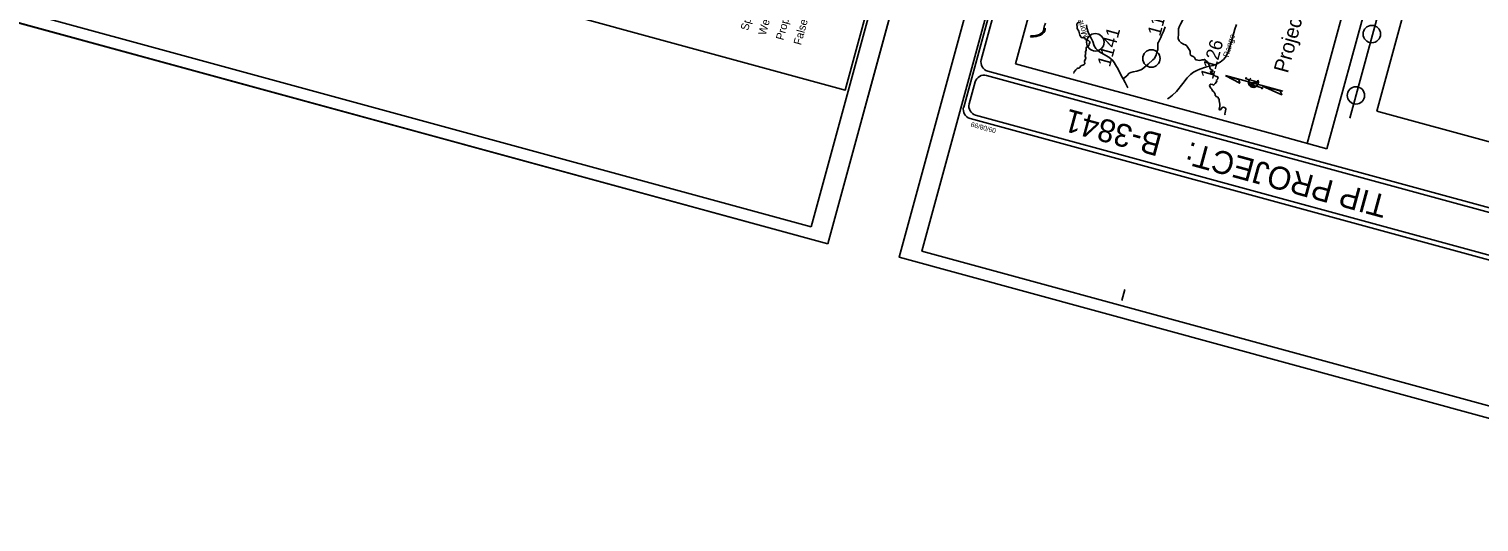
# Model space of a CAD drawing. Extents: x 2076126 to 2079903, y 925480 to 928006.
# Drawn here: x 2077447 to 2079033, y 925480 to 926019 of the extents above; entities that cross this region are included whole.
import ezdxf

# ---------------------------------------------------------------- set-up
doc = ezdxf.new("R2010")
doc.units = 0
for name, color, linetype in [('Default', 7, 'Continuous'), ('Old_Level_11', 7, 'Continuous'), ('Old_Level_31', 7, 'Continuous'), ('Old_Level_32', 7, 'Continuous'), ('Old_Level_50', 7, 'Continuous'), ('Old_Level_59', 7, 'Continuous'), ('Old_Level_8', 7, 'Continuous'), ('Prop Roadway Bridge', 7, 'Continuous'), ('Prop Shade Heavy', 7, 'Continuous'), ('Prop Shade Light', 7, 'Continuous'), ('Sheet Cutting Line CELL', 7, 'Continuous'), ('Sheet North Arrow CELL', 7, 'Continuous'), ('Sheet Plot Border Inside CELL', 7, 'Continuous'), ('Sheet Plot Border Outside CELL', 7, 'Continuous'), ('Sheet Symbology CELL', 7, 'Continuous'), ('Sheet Title CELL', 7, 'Continuous')]:
    doc.layers.add(name, color=color, linetype=linetype)

msp = doc.modelspace()

# ---------------------------------------------------------------- linework, layer by layer
at = {"layer": 'Default'}
for p, q in [((2078643.2, 926410.7), (2078526.1, 925981.2)), ((2078845, 925894.2), (2078962.2, 926323.7)), ((2078984, 926317.8), (2078866.8, 925888.3)), ((2078526.1, 925981.2), (2078816.9, 925901.9)), ((2078866.8, 925888.3), (2078816.9, 925901.9))]:
    msp.add_line(p, q, dxfattribs=at)
at = {"layer": 'Old_Level_31'}
msp.add_line((2078738.5, 925978.5), (2078738.5, 925978.5), dxfattribs=at)
at = {"layer": 'Old_Level_32'}
for points in [[(2078643.9, 925964.6), (2078641.8, 925968.4), (2078638.3, 925975.2), (2078635.6, 925980.2), (2078634.1, 925982.6), (2078632.4, 925985), (2078630.6, 925986.6), (2078628.3, 925988.5), (2078622.4, 925991.8), (2078618, 925994.4), (2078615.9, 925996), (2078614.2, 925998), (2078612.3, 926001), (2078610.7, 926005.5), (2078608.9, 926009.4), (2078606, 926014.7), (2078604.3, 926020.6), (2078603.9, 926023.9)], [(2078643.9, 925964.6), (2078647.8, 925968.1), (2078650.6, 925970.8), (2078652.2, 925971.8), (2078654.7, 925972.4), (2078658.8, 925973.2), (2078661, 925973.8), (2078663.1, 925974.5), (2078664.8, 925975.4), (2078671.1, 925980.9), (2078676.5, 925985.6), (2078678.1, 925987.1), (2078679.1, 925988.9), (2078679.9, 925990.7), (2078680.8, 925993.9), (2078681.8, 925997), (2078681.7, 926000), (2078682, 926003.8), (2078682.4, 926004.9), (2078683.6, 926007.2), (2078685, 926010.1), (2078686.4, 926012.9), (2078687.9, 926016.5), (2078689.8, 926021.8)], [(2078692.3, 925942.9), (2078694.2, 925944), (2078698, 925947), (2078702.1, 925950.8), (2078709.1, 925959.6), (2078713.9, 925965.7), (2078717.5, 925969.5), (2078720.7, 925971.9), (2078724.5, 925974), (2078727.7, 925975.5), (2078733.9, 925977.4), (2078738.5, 925978.5), (2078742.4, 925979.5), (2078746.1, 925980.7), (2078750.1, 925982.9), (2078753.7, 925986), (2078755.7, 925988.5), (2078758.9, 925994), (2078762.7, 926007.2), (2078766.1, 926018.9), (2078767.8, 926024.2)], [(2078649.2, 925954.8), (2078646, 925960.8), (2078643.9, 925964.6)]]:
    msp.add_lwpolyline(points, dxfattribs=at)
at = {"layer": 'Old_Level_50'}
msp.add_line((2078738.5, 925978.5), (2078738.5, 925978.5), dxfattribs=at)
at = {"layer": 'Old_Level_59'}
for points in [[(2078713.5, 926059.2), (2078714.4, 926059.1), (2078715.8, 926059.3), (2078716.8, 926058.9), (2078718.5, 926058), (2078720.6, 926056.5), (2078721.2, 926055.9), (2078721.6, 926055), (2078722, 926053.9), (2078721.6, 926052), (2078720, 926049.2), (2078717.4, 926044.5), (2078716.9, 926043.6), (2078716.1, 926041.1), (2078711.4, 926032.6), (2078709.6, 926030), (2078706.8, 926024.5), (2078705.4, 926022.4), (2078704.6, 926019.5), (2078704.6, 926013.8), (2078704, 926008.7)], [(2078542.3, 926010.5), (2078542.7, 926010.6), (2078546, 926010.6), (2078548.8, 926011), (2078553.5, 926012.5), (2078555.7, 926014.1), (2078557.1, 926015.3), (2078558.3, 926016.7), (2078558.6, 926018.2), (2078558.6, 926020.1)], [(2078542.7, 926011.9), (2078545.2, 926011.8), (2078548.1, 926012.1), (2078552.4, 926013.3), (2078555.1, 926014.9), (2078555.8, 926015.6), (2078556.9, 926017.5), (2078557.7, 926021.6), (2078557.9, 926023.2), (2078558.5, 926024.6), (2078558.9, 926025.6)], [(2078597.1, 926026.5), (2078595.1, 926026.3), (2078594.2, 926025.9), (2078593.8, 926025.5), (2078593.3, 926023.9), (2078593.7, 926022.1), (2078593.7, 926019.7), (2078595.3, 926016.9), (2078596.7, 926012.6), (2078597.4, 926011.3), (2078597.5, 926010.7), (2078597.8, 926010.4), (2078598.5, 926010), (2078599.7, 926009.7), (2078600.6, 926009.8), (2078601.9, 926009.2), (2078602.8, 926007.8), (2078604.3, 926007.1), (2078606.1, 926006.5), (2078607.2, 926005.6), (2078607.3, 926005), (2078607.3, 926004.2), (2078606.7, 926002.9)], [(2078606.7, 926002.9), (2078606.3, 926000.7), (2078606.1, 926000.4), (2078605.6, 926000.3), (2078604.5, 925999.8), (2078603.9, 925999.3), (2078603.6, 925998.4), (2078603.4, 925995.6), (2078602.9, 925994.5), (2078602.8, 925993.5), (2078603, 925992.9), (2078602.3, 925990.4), (2078602.4, 925989.6), (2078603.2, 925987.3), (2078602.9, 925986.2), (2078601.8, 925984.3), (2078601.7, 925983.6), (2078602.1, 925981.3), (2078601.3, 925980.3), (2078597.3, 925978.6), (2078596.4, 925977.1), (2078595.9, 925976.6), (2078594.4, 925976.6), (2078593.6, 925976.2), (2078592.1, 925974.5), (2078590.4, 925972.3), (2078589.9, 925971.1), (2078589.9, 925971.1)], [(2078704, 926008.7), (2078705.2, 926006.3), (2078706.1, 926005.1), (2078707.4, 926004), (2078709.8, 926002.6), (2078710.7, 926002.3), (2078712.1, 926002.1), (2078713.5, 926001), (2078713.6, 926000.5)], [(2078719.9, 925989.5), (2078718.7, 925990), (2078717.7, 925990.7), (2078717.2, 925992.4), (2078717.2, 925994.7), (2078716.9, 925995.9), (2078714.5, 925998.9), (2078713.9, 926000.1), (2078713.5, 926000.6)], [(2078719.9, 925989.5), (2078721.1, 925988.9), (2078722, 925988), (2078723.2, 925985.8), (2078723.9, 925985.4), (2078727.5, 925984.9), (2078729, 925985.1), (2078730.2, 925985.6), (2078732, 925985.6), (2078732.5, 925985.8), (2078733.2, 925985.8), (2078733.6, 925985.4), (2078734, 925984.6), (2078734.5, 925984.5), (2078735.5, 925984.2), (2078736.3, 925983.4), (2078738, 925979.6), (2078738.5, 925978.5), (2078738.9, 925976.9), (2078739.7, 925975.1), (2078740.9, 925974.5), (2078741.5, 925974.1), (2078741.9, 925973.4), (2078741.9, 925973), (2078741.4, 925972.8), (2078740, 925972.9), (2078739.6, 925972.7), (2078739.6, 925972.1), (2078739.8, 925971.5), (2078740.5, 925971), (2078741.1, 925970.8), (2078742, 925970.6), (2078742.1, 925970.2), (2078742.2, 925969.7), (2078743.9, 925968.2), (2078744.4, 925967.9), (2078745.1, 925967.4), (2078745.7, 925967.2), (2078746.7, 925967.2), (2078747.2, 925966.9), (2078747.7, 925966.4), (2078747.5, 925965.9), (2078747.3, 925965.4), (2078747.4, 925964.6), (2078746.9, 925964.1), (2078746.2, 925963.7), (2078745.9, 925963.3), (2078746.2, 925962.4), (2078746.1, 925961.4), (2078744.7, 925959.8), (2078743.8, 925958.9), (2078743.2, 925958.1), (2078742.5, 925958), (2078741.7, 925958.6), (2078739.6, 925959), (2078738.8, 925958.3), (2078738.5, 925957), (2078739.7, 925954.5), (2078740.9, 925953.4), (2078741.8, 925951.6), (2078742.9, 925950.9), (2078743.5, 925950.2), (2078744.5, 925948), (2078744.7, 925946.8)], [(2078744.7, 925946.8), (2078745.8, 925945.5), (2078747.4, 925944.8), (2078747.7, 925944.6), (2078748, 925943.3), (2078749, 925942.6), (2078749, 925940.6), (2078749.6, 925937.2), (2078749.8, 925934.8), (2078749, 925931.6), (2078749.4, 925930.8), (2078750.3, 925930.7), (2078751.8, 925933), (2078753.4, 925933.8), (2078754.6, 925933.5), (2078755.5, 925933.1), (2078756, 925932.6), (2078756.1, 925931.5), (2078755.4, 925927.8), (2078755.3, 925926.6), (2078755.6, 925925.5)]]:
    msp.add_lwpolyline(points, dxfattribs=at)
at = {"layer": 'Prop Roadway Bridge'}
msp.add_lwpolyline([(2078921.5, 925929.3), (2079234.7, 927077.6), (2079619.8, 926972.5), (2079306.6, 925824.3)], close=True, dxfattribs=at)
at = {"layer": 'Prop Shade Heavy'}
msp.add_line((2078891.7, 925921.6), (2078964.2, 926187.4), dxfattribs=at)
at = {"layer": 'Prop Shade Light'}
for centre in [(2078915.9, 926013.7), (2078613.5, 926004.7), (2078674.8, 925987), (2078898.5, 925946.6)]:
    msp.add_circle(centre, 9.52, dxfattribs=at)
at = {"layer": 'Sheet Cutting Line CELL'}
for p, q in [((2078321, 925784.5), (2078764.2, 927409.2)), ((2077259.8, 926074), (2078321, 925784.5))]:
    msp.add_line(p, q, dxfattribs=at)
at = {"layer": 'Sheet North Arrow CELL'}
for p, q in [((2078818.4, 925951.4), (2078755.7, 925968.5)), ((2078818.4, 925951.4), (2078755.7, 925968.5)), ((2078778.1, 925964.9), (2078791, 925961.4)), ((2078778.1, 925964.9), (2078791, 925961.4)), ((2078789, 925962), (2078782.9, 925958.5)), ((2078789, 925962), (2078782.9, 925958.5)), ((2078782.9, 925958.5), (2078796, 925954.9)), ((2078782.9, 925958.5), (2078796, 925954.9)), ((2078783.4, 925965.4), (2078783.5, 925965.4)), ((2078783.4, 925965.4), (2078783.5, 925965.4)), ((2078789.5, 925961.8), (2078783.4, 925958.3)), ((2078789.5, 925961.8), (2078783.4, 925958.3)), ((2078783.4, 925958.3), (2078784.6, 925958)), ((2078783.4, 925958.3), (2078784.6, 925958)), ((2078790.7, 925961.5), (2078784.6, 925958)), ((2078784.6, 925958), (2078790.7, 925961.5)), ((2078790.7, 925961.5), (2078784.6, 925958)), ((2078784.6, 925958), (2078790.7, 925961.5)), ((2078791, 925961.4), (2078784.9, 925957.9)), ((2078791, 925961.4), (2078784.9, 925957.9)), ((2078790.7, 925961.5), (2078789.5, 925961.8)), ((2078790.7, 925961.5), (2078789.5, 925961.8))]:
    msp.add_line(p, q, dxfattribs=at)
for points in [[(2078756.1, 925967.9), (2078771.4, 925959.9), (2078770.6, 925964)], [(2078756.1, 925967.9), (2078771.4, 925959.9), (2078770.6, 925964)], [(2078796.2, 925956.9), (2078817.3, 925947.4), (2078815.5, 925951.7)], [(2078796.2, 925956.9), (2078817.3, 925947.4), (2078815.5, 925951.7)]]:
    msp.add_lwpolyline(points, close=True, dxfattribs=at)
for centre in [(2078778.3, 925965.4), (2078778.3, 925965.4), (2078795.9, 925954.4), (2078795.9, 925954.4)]:
    msp.add_circle(centre, 0.53, dxfattribs=at)
for centre, radius, start, end in [((2078786.4, 925960.8), 5.46, 122.5834, 27.1375), ((2078786.4, 925960.8), 5.46, 122.5834, 27.1375), ((2078786.6, 925961.4), 5.12, 127.8384, 23.3721), ((2078786.6, 925961.4), 5.12, 127.8384, 23.3721)]:
    msp.add_arc(centre, radius, start, end, dxfattribs=at)
at = {"layer": 'Sheet Plot Border Inside CELL'}
for points in [[(2078302.8, 925803), (2078741.3, 927410.7), (2077723.4, 927688.4), (2077284.9, 926080.6)], [(2079441.8, 925498.6), (2079880.3, 927106.4), (2078862.4, 927384), (2078423.9, 925776.2)]]:
    msp.add_lwpolyline(points, close=True, dxfattribs=at)
at = {"layer": 'Sheet Plot Border Outside CELL'}
for points in [[(2078321, 925784.5), (2078764.2, 927409.2), (2077702.9, 927698.6), (2077259.8, 926074)], [(2078841.9, 927394.2), (2078398.8, 925769.6), (2079460, 925480.1), (2079903.2, 927104.8)]]:
    msp.add_lwpolyline(points, close=True, dxfattribs=at)
at = {"layer": 'Sheet Symbology CELL'}
msp.add_lwpolyline([(2077722.6, 927675.6), (2077327.9, 926228.5), (2078339.9, 925952.5), (2078734.6, 927399.6)], close=True, dxfattribs=at)
at = {"layer": 'Sheet Title CELL'}
for p, q in [((2079301.4, 925753.5), (2078495.8, 925973.2)), ((2079478.5, 925700), (2078494.5, 925968.4)), ((2078642.4, 925722.3), (2078645.7, 925734.4)), ((2078642.4, 925722.3), (2078645.7, 925734.4))]:
    msp.add_line(p, q, dxfattribs=at)
for points in [[(2078859, 927361.6), (2078469.5, 925933.8)], [(2078862.5, 927355.5), (2078488.8, 925985.5)], [(2078482.2, 925961.4), (2078475.6, 925937.3)], [(2078482.6, 925925), (2079466.7, 925656.6)], [(2078476.5, 925921.5), (2079470.2, 925650.5)], [(2078476.5, 925921.5), (2079470.2, 925650.5)]]:
    msp.add_lwpolyline(points, dxfattribs=at)
for centre, start, end in [((2078498.4, 925982.9), 164.7434, 254.7434), ((2078491.8, 925958.8), 74.7434, 164.7434), ((2078479.1, 925931.2), 164.7434, 254.7434), ((2078485.2, 925934.7), 164.7434, 254.7434)]:
    msp.add_arc(centre, 10, start, end, dxfattribs=at)

# ---------------------------------------------------------------- texts
at = {"layer": 'Default'}
msp.add_text('Project Location', height=16.22, rotation=74.7434, dxfattribs=at).set_placement((2078823.9, 925970.2))
at = {"layer": 'Old_Level_11'}
for s, rotation, p in [('Moriah', 108.2213, (2078605.9, 926010.6)), ('Range', 74.1198, (2078759.3, 925987.9))]:
    msp.add_text(s, height=6.49, rotation=rotation, dxfattribs=at).set_placement(p)
at = {"layer": 'Old_Level_8'}
for s, p in [('1147', (2078684.3, 926010.6)), ('1141', (2078629.4, 925976.9)), ('1126', (2078742.1, 925963.4))]:
    msp.add_text(s, height=14.6, rotation=74.6315, dxfattribs=at).set_placement(p)
at = {"layer": 'Sheet Symbology CELL'}
for s, p in [('Proposed Lateral, Tail, Head Ditch', (2078272.3, 926006.4)), ('Spring', (2078233.7, 926016.9)), ('Wetland', (2078253, 926011.7)), ('False Sump', (2078291.6, 926001.1))]:
    msp.add_text(s, height=8.75, rotation=74.7434, dxfattribs=at).set_placement(p)
at = {"layer": 'Sheet Title CELL'}
for s, height, p in [('B-3841  ', 25, (2078688.2, 925903.8)), ('09/08/99', 5.25, (2078505.4, 925910.2)), ('TIP PROJECT:', 25, (2078934.8, 925836.5))]:
    msp.add_text(s, height=height, rotation=164.7434, dxfattribs=at).set_placement(p)

doc.saveas('drawing.dxf')
